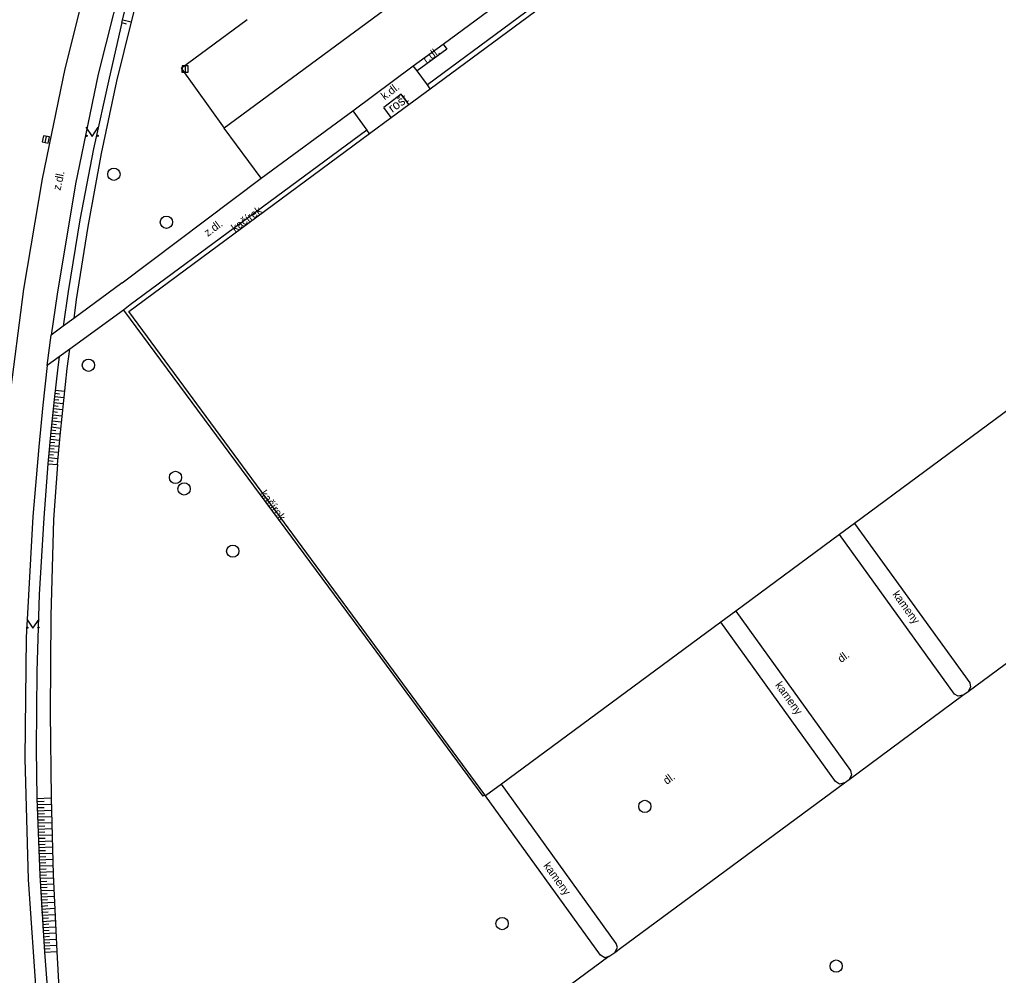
# Model space of a CAD drawing. Extents: x -596024 to -594475, y -1163820 to -1161957.
# Drawn here: x -594877.7 to -594798.2, y -1162768.8 to -1162691.2 of the extents above; entities that cross this region are included whole.
import ezdxf

# ---------------------------------------------------------------- set-up
doc = ezdxf.new("R2010")
doc.units = 0
for name, color, linetype in [('Level 10', 7, 'Continuous'), ('Level 11', 7, 'Continuous'), ('Level 14', 7, 'Continuous'), ('Level 15', 7, 'Continuous'), ('Level 27', 7, 'Continuous'), ('Level 36', 7, 'Continuous'), ('Level 40', 7, 'Continuous'), ('Level 42', 7, 'Continuous'), ('Level 5', 7, 'Continuous')]:
    doc.layers.add(name, color=color, linetype=linetype)

msp = doc.modelspace()

# ---------------------------------------------------------------- linework, layer by layer
at = {"layer": 'Level 10'}
for points in [[(-594861.88, -1162656.08), (-594865.46, -1162665.7), (-594868.68, -1162675.44), (-594871.55, -1162685.29), (-594874.05, -1162695.24)], [(-594858.09, -1162704.12), (-594850.65, -1162698.66), (-594845.75, -1162694.99), (-594843.32, -1162693.23), (-594832.19, -1162685)], [(-594864.59, -1162695.18), (-594859.22, -1162691.23)], [(-594874.05, -1162695.24), (-594875.88, -1162704.16), (-594877.39, -1162713.14), (-594878.56, -1162722.17), (-594879.41, -1162731.23)], [(-594864.59, -1162695.18), (-594861.1, -1162700.06)], [(-594858.09, -1162704.12), (-594861.1, -1162700.06)], [(-594809.91, -1162732.15), (-594800.54, -1162745.09), (-594800.49, -1162745.43)], [(-594801.49, -1162746.18), (-594801.79, -1162746.01), (-594811.13, -1162733.05)], [(-594819.55, -1162739.27), (-594810.22, -1162752.21), (-594810.15, -1162752.58)], [(-594811.11, -1162753.31), (-594811.43, -1162753.1), (-594820.75, -1162740.16)], [(-594801.09, -1162746.08), (-594801.49, -1162746.18)], [(-594801.09, -1162746.08), (-594800.67, -1162745.8)], [(-594800.49, -1162745.43), (-594800.67, -1162745.8)], [(-594810.71, -1162753.2), (-594811.11, -1162753.31)], [(-594810.71, -1162753.2), (-594810.32, -1162752.93)], [(-594810.15, -1162752.58), (-594810.32, -1162752.93)], [(-594829.27, -1162766.26), (-594838.58, -1162753.33)], [(-594829.36, -1162766.98), (-594829.16, -1162766.57)], [(-594829.16, -1162766.57), (-594829.27, -1162766.26)], [(-594829.84, -1162767.32), (-594866.26, -1162794.21)], [(-594829.84, -1162767.32), (-594829.36, -1162766.98)]]:
    msp.add_lwpolyline(points, dxfattribs=at)
at = {"layer": 'Level 11'}
for points in [[(-594749.93, -1162617.92), (-594763.42, -1162627.92), (-594795.24, -1162651.38), (-594814.4, -1162665.57), (-594834.38, -1162680.36), (-594861.1, -1162700.06)], [(-594859.32, -1162657.13), (-594862.85, -1162666.6), (-594866.03, -1162676.19), (-594868.86, -1162685.89), (-594871.33, -1162695.68)], [(-594816.78, -1162673.62), (-594815.64, -1162675.19), (-594831.09, -1162686.54), (-594844.58, -1162696.55)], [(-594843.32, -1162693.23), (-594843.02, -1162693.65), (-594845.41, -1162695.41)], [(-594844.58, -1162696.55), (-594845.41, -1162695.41), (-594845.75, -1162694.99)], [(-594871.33, -1162695.68), (-594873.17, -1162704.57), (-594874.67, -1162713.53), (-594875.15, -1162716.85)], [(-594844.36, -1162696.85), (-594844.58, -1162696.55)], [(-594846.71, -1162697.29), (-594848.13, -1162698.37)], [(-594846.09, -1162698.13), (-594846.71, -1162697.29)], [(-594847.53, -1162699.19), (-594848.13, -1162698.37)], [(-594850.65, -1162698.66), (-594849.5, -1162700.22)], [(-594849.5, -1162700.22), (-594868.73, -1162714.41)], [(-594849.3, -1162700.5), (-594849.5, -1162700.22)], [(-594869.39, -1162712.62), (-594858.09, -1162704.12)], [(-594869.39, -1162712.62), (-594873.31, -1162715.5), (-594874.18, -1162716.14), (-594875.15, -1162716.85)], [(-594868.73, -1162714.41), (-594869.27, -1162714.82), (-594873.64, -1162717.99), (-594874.5, -1162718.62), (-594875.48, -1162719.33)], [(-594869.27, -1162714.82), (-594849.61, -1162741.39)], [(-594875.48, -1162719.33), (-594875.15, -1162716.85)], [(-594875.48, -1162719.33), (-594875.83, -1162722.54), (-594876.138, -1162725.939), (-594876.65, -1162731.58)], [(-594800.67, -1162745.8), (-594776.85, -1162728.21)], [(-594876.65, -1162731.58), (-594877.17, -1162741.4), (-594877.29, -1162751.23), (-594877.01, -1162761.05), (-594876.33, -1162770.86)], [(-594849.61, -1162741.39), (-594840.1, -1162754.3)], [(-594810.32, -1162752.93), (-594801.09, -1162746.08)], [(-594828.9, -1162766.64), (-594810.71, -1162753.2)], [(-594839.93, -1162754.17), (-594840.1, -1162754.3)], [(-594830.53, -1162767.2), (-594839.86, -1162754.27)], [(-594829.36, -1162766.98), (-594828.9, -1162766.64)], [(-594829.84, -1162767.32), (-594830.19, -1162767.42), (-594830.53, -1162767.2)]]:
    msp.add_lwpolyline(points, dxfattribs=at)
at = {"layer": 'Level 14'}
for points in [[(-594869.4, -1162691.49), (-594868.75, -1162688.89), (-594868.07, -1162686.28), (-594867.37, -1162683.69), (-594866.64, -1162681.1)], [(-594865.93, -1162681.31), (-594866.64, -1162683.83), (-594867.34, -1162686.35), (-594868.01, -1162688.89), (-594868.66, -1162691.42)], [(-594869.4, -1162691.49), (-594870.45, -1162695.99)], [(-594868.66, -1162691.42), (-594869.83, -1162696.23)], [(-594870.45, -1162695.99), (-594871.72, -1162701.73)], [(-594869.83, -1162696.23), (-594871.08, -1162702.12)], [(-594871.72, -1162701.73), (-594872.83, -1162707.51)], [(-594871.08, -1162702.12), (-594872.17, -1162708.04)], [(-594872.83, -1162707.51), (-594873.78, -1162713.31)], [(-594872.17, -1162708.04), (-594873.11, -1162713.98)], [(-594873.78, -1162713.31), (-594874.18, -1162716.14)], [(-594873.11, -1162713.98), (-594873.31, -1162715.5)], [(-594874.62, -1162727.37), (-594874.39, -1162724.76), (-594874.13, -1162722.16), (-594873.84, -1162719.56), (-594873.64, -1162717.99)], [(-594874.5, -1162718.62), (-594874.61, -1162719.47), (-594874.91, -1162722.08), (-594875.18, -1162724.69), (-594875.42, -1162727.3)], [(-594875.42, -1162727.3), (-594875.74, -1162731.68)], [(-594874.62, -1162727.37), (-594874.95, -1162731.82)], [(-594875.74, -1162731.68), (-594876.11, -1162737.93)], [(-594874.95, -1162731.82), (-594875.17, -1162739.65)], [(-594876.11, -1162737.93), (-594876.31, -1162744.18)], [(-594875.17, -1162739.65), (-594875.24, -1162747.49)], [(-594876.31, -1162744.18), (-594876.36, -1162750.44)], [(-594875.24, -1162747.49), (-594875.16, -1162754.43)], [(-594876.36, -1162750.44), (-594876.3, -1162754.47)], [(-594876.3, -1162754.47), (-594876.08, -1162760.71), (-594875.7, -1162766.95)], [(-594875.16, -1162754.43), (-594874.98, -1162760.66), (-594874.7, -1162766.89)], [(-594875.7, -1162766.95), (-594875.39, -1162770.82)], [(-594874.7, -1162766.89), (-594874.47, -1162770.89)]]:
    msp.add_lwpolyline(points, dxfattribs=at)
at = {"layer": 'Level 15'}
for points in [[(-594869.34, -1162691.25), (-594868.66, -1162691.42)], [(-594869.4, -1162691.49), (-594869.06, -1162691.58)], [(-594874.83, -1162721.33), (-594874.05, -1162721.41)], [(-594874.94, -1162722.32), (-594874.16, -1162722.41)], [(-594874.91, -1162722.08), (-594874.52, -1162722.12)], [(-594874.89, -1162721.83), (-594874.1, -1162721.91)], [(-594874.86, -1162721.58), (-594874.46, -1162721.62)], [(-594875.02, -1162723.07), (-594874.62, -1162723.11)], [(-594874.99, -1162722.82), (-594874.21, -1162722.91)], [(-594874.96, -1162722.57), (-594874.57, -1162722.62)], [(-594875.1, -1162723.82), (-594874.31, -1162723.9)], [(-594875.07, -1162723.57), (-594874.67, -1162723.61)], [(-594875.04, -1162723.32), (-594874.26, -1162723.4)], [(-594875.17, -1162724.56), (-594874.77, -1162724.61)], [(-594875.14, -1162724.31), (-594874.36, -1162724.4)], [(-594875.12, -1162724.07), (-594874.72, -1162724.11)], [(-594875.24, -1162725.31), (-594874.45, -1162725.38)], [(-594875.22, -1162725.06), (-594874.82, -1162725.1)], [(-594875.19, -1162724.81), (-594874.4, -1162724.88)], [(-594875.31, -1162726.06), (-594874.91, -1162726.09)], [(-594875.29, -1162725.81), (-594874.49, -1162725.88)], [(-594875.26, -1162725.56), (-594874.86, -1162725.59)], [(-594875.39, -1162727.05), (-594874.99, -1162727.09)], [(-594875.37, -1162726.8), (-594874.58, -1162726.87)], [(-594875.34, -1162726.56), (-594874.95, -1162726.59)], [(-594875.33, -1162726.31), (-594874.54, -1162726.37)], [(-594875.42, -1162727.3), (-594874.62, -1162727.37)], [(-594876.3, -1162754.47), (-594875.16, -1162754.43)], [(-594876.29, -1162754.72), (-594875.72, -1162754.7)], [(-594876.29, -1162754.97), (-594875.15, -1162754.93)], [(-594876.28, -1162755.22), (-594875.71, -1162755.2)], [(-594876.28, -1162755.47), (-594875.14, -1162755.43)], [(-594876.27, -1162755.72), (-594875.69, -1162755.7)], [(-594876.26, -1162755.97), (-594875.12, -1162755.93)], [(-594876.25, -1162756.47), (-594875.11, -1162756.43)], [(-594876.24, -1162756.22), (-594875.68, -1162756.2)], [(-594876.24, -1162756.72), (-594875.67, -1162756.7)], [(-594876.23, -1162756.96), (-594875.1, -1162756.93)], [(-594876.22, -1162757.21), (-594875.65, -1162757.2)], [(-594876.22, -1162757.46), (-594875.09, -1162757.43)], [(-594876.21, -1162757.71), (-594875.64, -1162757.7)], [(-594876.2, -1162757.96), (-594875.07, -1162757.93)], [(-594876.19, -1162758.21), (-594875.63, -1162758.19)], [(-594876.18, -1162758.46), (-594875.06, -1162758.41)], [(-594876.17, -1162758.71), (-594875.61, -1162758.69)], [(-594876.16, -1162758.96), (-594875.04, -1162758.91)], [(-594876.15, -1162759.21), (-594875.59, -1162759.19)], [(-594876.14, -1162759.46), (-594875.02, -1162759.41)], [(-594876.13, -1162759.71), (-594875.57, -1162759.69)], [(-594876.12, -1162759.96), (-594875.01, -1162759.91)], [(-594876.11, -1162760.21), (-594875.55, -1162760.19)], [(-594876.08, -1162760.46), (-594874.99, -1162760.41)], [(-594876.08, -1162760.71), (-594875.53, -1162760.69)], [(-594876.07, -1162760.96), (-594874.97, -1162760.91)], [(-594876.06, -1162761.21), (-594875.51, -1162761.19)], [(-594876.05, -1162761.46), (-594874.95, -1162761.41)], [(-594876.03, -1162761.71), (-594875.48, -1162761.69)], [(-594876.02, -1162761.96), (-594874.93, -1162761.91)], [(-594876.01, -1162762.21), (-594875.46, -1162762.19)], [(-594875.99, -1162762.46), (-594874.91, -1162762.41)], [(-594875.98, -1162762.71), (-594875.44, -1162762.67)], [(-594875.96, -1162762.96), (-594874.89, -1162762.89)], [(-594875.95, -1162763.21), (-594875.41, -1162763.17)], [(-594875.94, -1162763.46), (-594874.87, -1162763.39)], [(-594875.92, -1162763.71), (-594875.39, -1162763.67)], [(-594875.91, -1162763.96), (-594874.85, -1162763.89)], [(-594875.89, -1162764.21), (-594875.36, -1162764.17)], [(-594875.87, -1162764.46), (-594874.83, -1162764.39)], [(-594875.86, -1162764.71), (-594875.33, -1162764.67)], [(-594875.84, -1162764.96), (-594874.8, -1162764.89)], [(-594875.82, -1162765.2), (-594875.3, -1162765.17)], [(-594875.81, -1162765.45), (-594874.78, -1162765.39)], [(-594875.79, -1162765.7), (-594875.28, -1162765.67)], [(-594875.78, -1162765.95), (-594874.75, -1162765.89)], [(-594875.76, -1162766.2), (-594875.25, -1162766.17)], [(-594875.74, -1162766.45), (-594874.73, -1162766.39)], [(-594875.72, -1162766.7), (-594875.22, -1162766.67)], [(-594875.7, -1162766.95), (-594874.7, -1162766.89)]]:
    msp.add_lwpolyline(points, dxfattribs=at)
at = {"layer": 'Level 27'}
for p, q in [((-594864.268, -1162695), (-594864.272, -1162695.5)), ((-594875.628, -1162701.215), (-594875.532, -1162700.725))]:
    msp.add_line(p, q, dxfattribs=at)
for points in [[(-594864.518, -1162694.998), (-594864.522, -1162695.498), (-594864.022, -1162695.502), (-594864.018, -1162695.002)], [(-594875.383, -1162701.263), (-594875.286, -1162700.773), (-594875.777, -1162700.676), (-594875.874, -1162701.167)]]:
    msp.add_lwpolyline(points, close=True, dxfattribs=at)
for centre in [(-594870.05, -1162703.8), (-594865.79, -1162707.69), (-594872.12, -1162719.3), (-594865.05, -1162728.41), (-594864.35, -1162729.35), (-594860.4, -1162734.4), (-594826.93, -1162755.12), (-594838.52, -1162764.64), (-594811.39, -1162768.09)]:
    msp.add_circle(centre, 0.5, dxfattribs=at)
at = {"layer": 'Level 36'}
for points in [[(-594872.32, -1162699.98), (-594871.82, -1162700.73), (-594871.32, -1162699.98)], [(-594877.13, -1162739.91), (-594876.63, -1162740.66), (-594876.13, -1162739.91)]]:
    msp.add_lwpolyline(points, dxfattribs=at)
for centre in [(-594872.27, -1162700.68), (-594871.371, -1162700.68), (-594877.08, -1162740.61), (-594876.181, -1162740.61)]:
    msp.add_circle(centre, 0.05, dxfattribs=at)
at = {"layer": 'Level 5'}
for points in [[(-594868.84, -1162714.93), (-594849.3, -1162700.5), (-594847.53, -1162699.19), (-594846.09, -1162698.13), (-594844.36, -1162696.85), (-594815.42, -1162675.48), (-594814.93, -1162675.12), (-594813.5, -1162674.07), (-594813.05, -1162673.74), (-594793.72, -1162659.47), (-594793.23, -1162659.11), (-594791.8, -1162658.05), (-594791.34, -1162657.71), (-594764.75, -1162638.08), (-594764.27, -1162637.72), (-594762.84, -1162636.67), (-594762.37, -1162636.32), (-594742.69, -1162621.79)], [(-594743.63, -1162683.19), (-594756.89, -1162692.99), (-594758.15, -1162693.92), (-594766.49, -1162700.08), (-594767.71, -1162700.98), (-594771.36, -1162703.67), (-594772.63, -1162704.61), (-594780.96, -1162710.77), (-594782.17, -1162711.66), (-594785.81, -1162714.35), (-594787.04, -1162715.26), (-594809.91, -1162732.15), (-594811.13, -1162733.05), (-594819.55, -1162739.27), (-594820.75, -1162740.16), (-594838.58, -1162753.33), (-594839.86, -1162754.27)], [(-594839.86, -1162754.27), (-594839.93, -1162754.17), (-594868.84, -1162714.93)]]:
    msp.add_lwpolyline(points, dxfattribs=at)

# ---------------------------------------------------------------- texts
at = {"layer": 'Level 40'}
for s, rotation, p in [('r.dl.', 36, (-594844.68, -1162694.81)), ('k.dl.', 37.25529, (-594848.06, -1162697.8)), ('z.dl.', 77.85, (-594874.39, -1162705.15)), ('kačírek', 36, (-594860.22, -1162708.52)), ('z.dl.', 36.42397, (-594862.43, -1162708.89)), ('kačírek', 306, (-594858.22, -1162729.74)), ('kameny', 305.89267, (-594806.85, -1162737.91)), ('dl.', 36, (-594810.98, -1162743.49)), ('kameny', 305.79712, (-594816.38, -1162745.28)), ('dl.', 36, (-594825.15, -1162753.38)), ('kameny', 305.79712, (-594835.2, -1162759.94))]:
    msp.add_text(s, height=0.65, rotation=rotation, dxfattribs=at).set_placement(p)
at = {"layer": 'Level 42'}
msp.add_text('rošt', height=0.75, rotation=36, dxfattribs=at).set_placement((-594847.44, -1162698.83))

doc.saveas('drawing.dxf')
